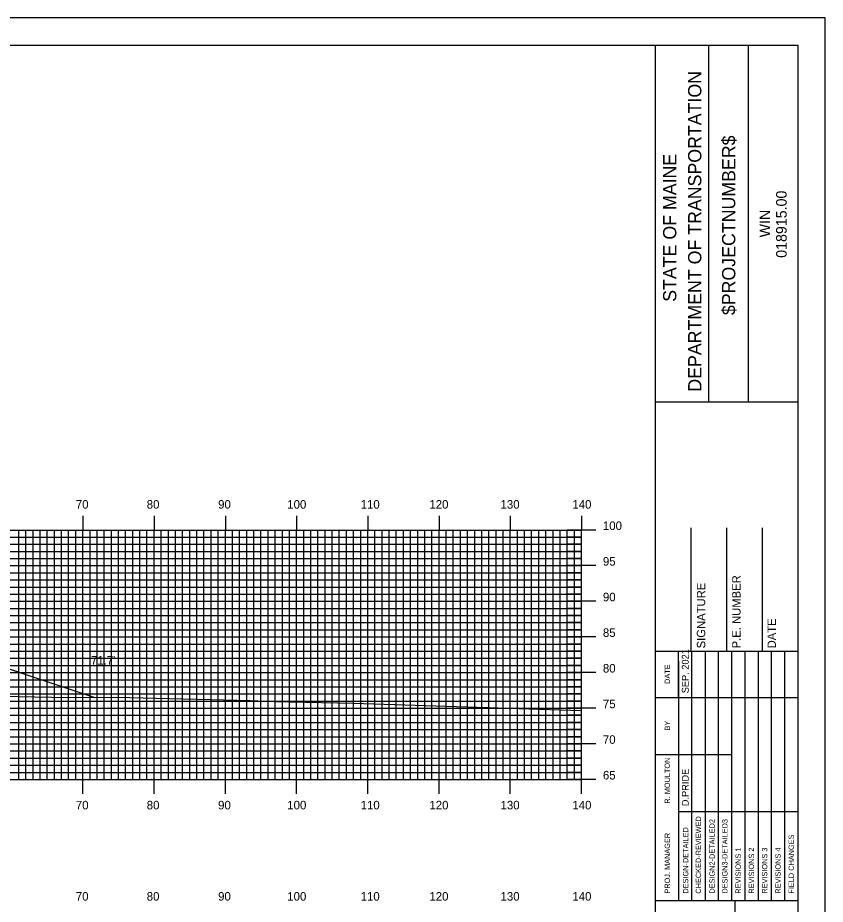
# Model space of a CAD drawing. Extents: x 1775957 to 1776301, y 442591 to 442811.
# Drawn here: x 1776184.1 to 1776297.4, y 442686.2 to 442810.5 of the extents above; entities that cross this region are included whole.
import ezdxf

# ---------------------------------------------------------------- set-up
doc = ezdxf.new("R2010")
doc.units = 0
for name, color, linetype in [('BORDER', 7, 'Continuous'), ('D_Roadway_Centerline', 7, 'Continuous'), ('D_Roadway_SlopeLines', 7, 'Continuous'), ('D_Text_Standard', 7, 'Continuous'), ('H_V ANNOTATION', 7, 'Continuous'), ('MAJOR', 7, 'Continuous'), ('MINOR', 7, 'Continuous'), ('PLOT BOUNDARY', 7, 'Continuous'), ('S_Roadway_Centerline', 7, 'Continuous')]:
    doc.layers.add(name, color=color, linetype=linetype)

msp = doc.modelspace()

# ---------------------------------------------------------------- linework, layer by layer
at = {"layer": 'BORDER'}
for p, q in [((1776273.62, 442596.67), (1776273.62, 442806.67)), ((1776281.08, 442756.66), (1776281.08, 442806.66)), ((1776286.67, 442756.66), (1776286.67, 442806.66)), ((1776273.63, 442756.65), (1776293.62, 442756.65)), ((1776278.62, 442721.67), (1776278.62, 442738.97)), ((1776283.62, 442721.67), (1776283.62, 442738.97)), ((1776288.62, 442721.67), (1776288.62, 442738.97)), ((1776273.62, 442721.67), (1776293.62, 442721.67)), ((1776273.62, 442686.67), (1776293.62, 442686.67)), ((1776284.81, 442616.67), (1776284.81, 442686.67))]:
    msp.add_line(p, q, dxfattribs=at)
msp.add_lwpolyline([(1775973.62, 442596.67), (1776293.62, 442596.67), (1776293.62, 442806.67), (1775973.62, 442806.67)], close=True, dxfattribs=at)
for points in [[(1776276.85, 442715.17), (1776276.85, 442721.67)], [(1776278.72, 442686.68), (1776278.72, 442721.67)], [(1776280.58, 442721.67), (1776280.58, 442686.68)], [(1776282.45, 442686.68), (1776282.45, 442721.67)], [(1776284.31, 442686.68), (1776284.31, 442721.67)], [(1776286.17, 442686.68), (1776286.17, 442721.67)], [(1776288.04, 442686.68), (1776288.04, 442721.67)], [(1776289.9, 442686.68), (1776289.9, 442721.67)], [(1776291.76, 442686.68), (1776291.76, 442721.67)], [(1776276.86, 442686.68), (1776276.86, 442720.26)], [(1776273.62, 442715.17), (1776293.62, 442715.17)], [(1776273.62, 442707.17), (1776276.86, 442707.17)], [(1776276.85, 442707.17), (1776284.31, 442707.17)], [(1776276.85, 442699.17), (1776293.62, 442699.17)]]:
    msp.add_lwpolyline(points, dxfattribs=at)
at = {"layer": 'D_Roadway_Centerline'}
msp.add_lwpolyline([(1776153.51, 442728.99), (1776194.92, 442715.18)], dxfattribs=at)
at = {"layer": 'D_Roadway_SlopeLines'}
msp.add_lwpolyline([(1776146.22, 442731.41), (1776194.92, 442715.18)], dxfattribs=at)
at = {"layer": 'MAJOR'}
for p, q in [((1776193.22, 442740.67), (1776193.22, 442738.67)), ((1776203.22, 442740.67), (1776203.22, 442738.67)), ((1776213.22, 442740.67), (1776213.22, 442738.67)), ((1776223.22, 442740.67), (1776223.22, 442738.67)), ((1776233.22, 442740.67), (1776233.22, 442738.67)), ((1776243.22, 442740.67), (1776243.22, 442738.67)), ((1776253.22, 442740.67), (1776253.22, 442738.67)), ((1776263.22, 442740.67), (1776263.22, 442738.67)), ((1775983.22, 442738.67), (1776263.22, 442738.67)), ((1775983.22, 442738.67), (1776263.22, 442738.67)), ((1776193.22, 442703.67), (1776193.22, 442738.67)), ((1776203.22, 442703.67), (1776203.22, 442738.67)), ((1776213.22, 442703.67), (1776213.22, 442738.67)), ((1776223.22, 442703.67), (1776223.22, 442738.67)), ((1776233.22, 442703.67), (1776233.22, 442738.67)), ((1776243.22, 442703.67), (1776243.22, 442738.67)), ((1776253.22, 442703.67), (1776253.22, 442738.67)), ((1776265.23, 442738.67), (1776261.22, 442738.67)), ((1776263.22, 442703.67), (1776263.22, 442738.67)), ((1776263.22, 442703.67), (1776263.22, 442738.67)), ((1775983.22, 442733.67), (1776263.22, 442733.67)), ((1776265.23, 442733.67), (1776261.22, 442733.67)), ((1775983.22, 442728.67), (1776263.22, 442728.67)), ((1776265.23, 442728.67), (1776261.22, 442728.67)), ((1775983.22, 442723.67), (1776263.22, 442723.67)), ((1776265.23, 442723.67), (1776261.22, 442723.67)), ((1775983.22, 442718.67), (1776263.22, 442718.67)), ((1776265.23, 442718.67), (1776261.22, 442718.67)), ((1775983.22, 442713.67), (1776263.22, 442713.67)), ((1776265.23, 442713.67), (1776261.22, 442713.67)), ((1775983.22, 442708.67), (1776263.22, 442708.67)), ((1776265.23, 442708.67), (1776261.22, 442708.67)), ((1775983.22, 442703.67), (1776263.22, 442703.67)), ((1775983.22, 442703.67), (1776263.22, 442703.67)), ((1776193.22, 442701.66), (1776193.22, 442703.67)), ((1776203.22, 442701.66), (1776203.22, 442703.67)), ((1776213.22, 442701.66), (1776213.22, 442703.67)), ((1776223.22, 442701.66), (1776223.22, 442703.67)), ((1776233.22, 442701.66), (1776233.22, 442703.67)), ((1776243.22, 442701.66), (1776243.22, 442703.67)), ((1776253.22, 442701.66), (1776253.22, 442703.67)), ((1776265.23, 442703.67), (1776261.22, 442703.67)), ((1776263.22, 442701.66), (1776263.22, 442703.67))]:
    msp.add_line(p, q, dxfattribs=at)
at = {"layer": 'MINOR'}
for p, q in [((1775983.22, 442737.67), (1776263.22, 442737.67)), ((1776184.22, 442703.67), (1776184.22, 442738.67)), ((1776185.22, 442703.67), (1776185.22, 442738.67)), ((1776186.22, 442703.67), (1776186.22, 442738.67)), ((1776187.22, 442703.67), (1776187.22, 442738.67)), ((1776188.22, 442703.67), (1776188.22, 442738.67)), ((1776189.22, 442703.67), (1776189.22, 442738.67)), ((1776190.22, 442703.67), (1776190.22, 442738.67)), ((1776191.22, 442703.67), (1776191.22, 442738.67)), ((1776192.22, 442703.67), (1776192.22, 442738.67)), ((1776194.22, 442703.67), (1776194.22, 442738.67)), ((1776195.22, 442703.67), (1776195.22, 442738.67)), ((1776196.22, 442703.67), (1776196.22, 442738.67)), ((1776197.22, 442703.67), (1776197.22, 442738.67)), ((1776198.22, 442703.67), (1776198.22, 442738.67)), ((1776199.22, 442703.67), (1776199.22, 442738.67)), ((1776200.22, 442703.67), (1776200.22, 442738.67)), ((1776201.22, 442703.67), (1776201.22, 442738.67)), ((1776202.22, 442703.67), (1776202.22, 442738.67)), ((1776204.22, 442703.67), (1776204.22, 442738.67)), ((1776205.22, 442703.67), (1776205.22, 442738.67)), ((1776206.22, 442703.67), (1776206.22, 442738.67)), ((1776207.22, 442703.67), (1776207.22, 442738.67)), ((1776208.22, 442703.67), (1776208.22, 442738.67)), ((1776209.22, 442703.67), (1776209.22, 442738.67)), ((1776210.22, 442703.67), (1776210.22, 442738.67)), ((1776211.22, 442703.67), (1776211.22, 442738.67)), ((1776212.22, 442703.67), (1776212.22, 442738.67)), ((1776214.22, 442703.67), (1776214.22, 442738.67)), ((1776215.22, 442703.67), (1776215.22, 442738.67)), ((1776216.22, 442703.67), (1776216.22, 442738.67)), ((1776217.22, 442703.67), (1776217.22, 442738.67)), ((1776218.22, 442703.67), (1776218.22, 442738.67)), ((1776219.22, 442703.67), (1776219.22, 442738.67)), ((1776220.22, 442703.67), (1776220.22, 442738.67)), ((1776221.22, 442703.67), (1776221.22, 442738.67)), ((1776222.22, 442703.67), (1776222.22, 442738.67)), ((1776224.22, 442703.67), (1776224.22, 442738.67)), ((1776225.22, 442703.67), (1776225.22, 442738.67)), ((1776226.22, 442703.67), (1776226.22, 442738.67)), ((1776227.22, 442703.67), (1776227.22, 442738.67)), ((1776228.22, 442703.67), (1776228.22, 442738.67)), ((1776229.22, 442703.67), (1776229.22, 442738.67)), ((1776230.22, 442703.67), (1776230.22, 442738.67)), ((1776231.22, 442703.67), (1776231.22, 442738.67)), ((1776232.22, 442703.67), (1776232.22, 442738.67)), ((1776234.22, 442703.67), (1776234.22, 442738.67)), ((1776235.22, 442703.67), (1776235.22, 442738.67)), ((1776236.22, 442703.67), (1776236.22, 442738.67)), ((1776237.22, 442703.67), (1776237.22, 442738.67)), ((1776238.22, 442703.67), (1776238.22, 442738.67)), ((1776239.22, 442703.67), (1776239.22, 442738.67)), ((1776240.22, 442703.67), (1776240.22, 442738.67)), ((1776241.22, 442703.67), (1776241.22, 442738.67)), ((1776242.22, 442703.67), (1776242.22, 442738.67)), ((1776244.22, 442703.67), (1776244.22, 442738.67)), ((1776245.22, 442703.67), (1776245.22, 442738.67)), ((1776246.22, 442703.67), (1776246.22, 442738.67)), ((1776247.22, 442703.67), (1776247.22, 442738.67)), ((1776248.22, 442703.67), (1776248.22, 442738.67)), ((1776249.22, 442703.67), (1776249.22, 442738.67)), ((1776250.22, 442703.67), (1776250.22, 442738.67)), ((1776251.22, 442703.67), (1776251.22, 442738.67)), ((1776252.22, 442703.67), (1776252.22, 442738.67)), ((1776254.22, 442703.67), (1776254.22, 442738.67)), ((1776255.22, 442703.67), (1776255.22, 442738.67)), ((1776256.22, 442703.67), (1776256.22, 442738.67)), ((1776257.22, 442703.67), (1776257.22, 442738.67)), ((1776258.22, 442703.67), (1776258.22, 442738.67)), ((1776259.22, 442703.67), (1776259.22, 442738.67)), ((1776260.22, 442703.67), (1776260.22, 442738.67)), ((1776261.22, 442703.67), (1776261.22, 442738.67)), ((1776263.22, 442737.67), (1776261.22, 442737.67)), ((1776262.22, 442703.67), (1776262.22, 442738.67)), ((1775983.22, 442736.67), (1776263.22, 442736.67)), ((1776263.22, 442736.67), (1776261.22, 442736.67)), ((1775983.22, 442735.67), (1776263.22, 442735.67)), ((1776263.22, 442735.67), (1776261.22, 442735.67)), ((1775983.22, 442734.67), (1776263.22, 442734.67)), ((1776263.22, 442734.67), (1776261.22, 442734.67)), ((1775983.22, 442732.67), (1776263.22, 442732.67)), ((1776263.22, 442732.67), (1776261.22, 442732.67)), ((1775983.22, 442731.67), (1776263.22, 442731.67)), ((1776263.22, 442731.67), (1776261.22, 442731.67)), ((1775983.22, 442730.67), (1776263.22, 442730.67)), ((1776263.22, 442730.67), (1776261.22, 442730.67)), ((1775983.22, 442729.67), (1776263.22, 442729.67)), ((1776263.22, 442729.67), (1776261.22, 442729.67)), ((1775983.22, 442727.67), (1776263.22, 442727.67)), ((1776263.22, 442727.67), (1776261.22, 442727.67)), ((1775983.22, 442726.67), (1776263.22, 442726.67)), ((1776263.22, 442726.67), (1776261.22, 442726.67)), ((1775983.22, 442725.67), (1776263.22, 442725.67)), ((1776263.22, 442725.67), (1776261.22, 442725.67)), ((1775983.22, 442724.67), (1776263.22, 442724.67)), ((1776263.22, 442724.67), (1776261.22, 442724.67)), ((1775983.22, 442722.67), (1776263.22, 442722.67)), ((1776263.22, 442722.67), (1776261.22, 442722.67)), ((1775983.22, 442721.67), (1776263.22, 442721.67)), ((1776263.22, 442721.67), (1776261.22, 442721.67)), ((1775983.22, 442720.67), (1776263.22, 442720.67)), ((1776263.22, 442720.67), (1776261.22, 442720.67)), ((1775983.22, 442719.67), (1776263.22, 442719.67)), ((1776263.22, 442719.67), (1776261.22, 442719.67)), ((1775983.22, 442717.67), (1776263.22, 442717.67)), ((1776263.22, 442717.67), (1776261.22, 442717.67)), ((1775983.22, 442716.67), (1776263.22, 442716.67)), ((1776263.22, 442716.67), (1776261.22, 442716.67)), ((1775983.22, 442715.67), (1776263.22, 442715.67)), ((1776263.22, 442715.67), (1776261.22, 442715.67)), ((1775983.22, 442714.67), (1776263.22, 442714.67)), ((1776263.22, 442714.67), (1776261.22, 442714.67)), ((1775983.22, 442712.67), (1776263.22, 442712.67)), ((1776263.22, 442712.67), (1776261.22, 442712.67)), ((1775983.22, 442711.67), (1776263.22, 442711.67)), ((1776263.22, 442711.67), (1776261.22, 442711.67)), ((1775983.22, 442710.67), (1776263.22, 442710.67)), ((1776263.22, 442710.67), (1776261.22, 442710.67)), ((1775983.22, 442709.67), (1776263.22, 442709.67)), ((1776263.22, 442709.67), (1776261.22, 442709.67)), ((1775983.22, 442707.67), (1776263.22, 442707.67)), ((1775983.22, 442706.67), (1776263.22, 442706.67)), ((1776263.22, 442707.67), (1776261.22, 442707.67)), ((1776263.22, 442706.67), (1776261.22, 442706.67)), ((1775983.22, 442705.67), (1776263.22, 442705.67)), ((1776263.22, 442705.67), (1776261.22, 442705.67)), ((1775983.22, 442704.67), (1776263.22, 442704.67)), ((1776263.22, 442704.67), (1776261.22, 442704.67))]:
    msp.add_line(p, q, dxfattribs=at)
at = {"layer": 'PLOT BOUNDARY'}
msp.add_lwpolyline([(1775957.44, 442590.55), (1776297.44, 442590.55), (1776297.44, 442810.55), (1775957.44, 442810.55)], close=True, dxfattribs=at)
at = {"layer": 'S_Roadway_Centerline'}
msp.add_lwpolyline([(1776177.22, 442715.41), (1776184.18, 442715.3), (1776191.09, 442715.16), (1776197.95, 442715.2), (1776216.7, 442714.73), (1776218.86, 442714.66), (1776220.07, 442714.6), (1776231.16, 442714.39), (1776263.11, 442713.35), (1776263.22, 442713.35)], dxfattribs=at)

# ---------------------------------------------------------------- texts
at = {"layer": 'BORDER'}
for s, height, p in [('DEPARTMENT OF TRANSPORTATION', 1.8635, (1776280.04, 442758.08)), ('$PROJECTNUMBER$', 1.8635, (1776284.81, 442768.82)), ('STATE OF MAINE', 1.8635, (1776276.53, 442770.69)), ('018915.00', 1.491, (1776292.02, 442776.86)), ('WIN', 1.491, (1776289.7, 442779.73)), ('P.E. NUMBER', 1.1811, (1776285.55, 442722.06)), ('SIGNATURE', 1.181, (1776280.59, 442722.06)), ('DATE', 1.181, (1776290.51, 442722.06)), ('SEP. 2021', 0.969, (1776278.27, 442715.76)), ('DATE', 0.743, (1776275.63, 442717.08)), ('BY', 0.743, (1776275.63, 442710.54)), ('R. MOULTON', 0.745, (1776275.63, 442700.28)), ('D.PRIDE', 0.969, (1776278.27, 442699.92)), ('CHECKED-REVIEWED', 0.7455, (1776279.99, 442687.65)), ('DESIGN2-DETAILED2', 0.7455, (1776281.92, 442687.65)), ('DESIGN3-DETAILED3', 0.7455, (1776283.71, 442687.65)), ('DESIGN-DETAILED', 0.7455, (1776278.2, 442687.65)), ('PROJ. MANAGER', 0.7455, (1776275.63, 442687.65)), ('FIELD CHANGES', 0.7455, (1776293.03, 442687.65)), ('REVISIONS 1', 0.7455, (1776285.58, 442687.65)), ('REVISIONS 2', 0.7455, (1776287.44, 442687.65)), ('REVISIONS 3', 0.7455, (1776289.3, 442687.65)), ('REVISIONS 4', 0.7455, (1776291.17, 442687.65))]:
    msp.add_text(s, height=height, rotation=90, dxfattribs=at).set_placement(p)
at = {"layer": 'D_Text_Standard'}
msp.add_text("71.7'", height=1.2, dxfattribs=at).set_placement((1776194.35, 442719.8))
at = {"layer": 'H_V ANNOTATION'}
for s, p in [('70', (1776192.23, 442741.67)), ('80', (1776202.18, 442741.67)), ('90', (1776212.2, 442741.67)), ('100', (1776221.91, 442741.67)), ('110', (1776232.21, 442741.67)), ('120', (1776241.86, 442741.67)), ('130', (1776251.85, 442741.67)), ('140', (1776261.93, 442741.67)), ('100', (1776266.22, 442738.67)), ('95', (1776266.22, 442733.67)), ('90', (1776266.22, 442728.67)), ('85', (1776266.22, 442723.67)), ('80', (1776266.22, 442718.67)), ('75', (1776266.22, 442713.67)), ('70', (1776266.22, 442708.67)), ('65', (1776266.22, 442703.67)), ('70', (1776192.23, 442699.47)), ('80', (1776202.18, 442699.47)), ('90', (1776212.2, 442699.47)), ('100', (1776221.91, 442699.47)), ('110', (1776232.21, 442699.47)), ('120', (1776241.86, 442699.47)), ('130', (1776251.85, 442699.47)), ('140', (1776261.93, 442699.47)), ('70', (1776192.23, 442686.67)), ('80', (1776202.18, 442686.67)), ('90', (1776212.2, 442686.67)), ('100', (1776221.91, 442686.67)), ('110', (1776232.21, 442686.67)), ('120', (1776241.86, 442686.67)), ('130', (1776251.85, 442686.67)), ('140', (1776261.93, 442686.67))]:
    msp.add_text(s, height=1.2, dxfattribs=at).set_placement(p)

doc.saveas('drawing.dxf')
